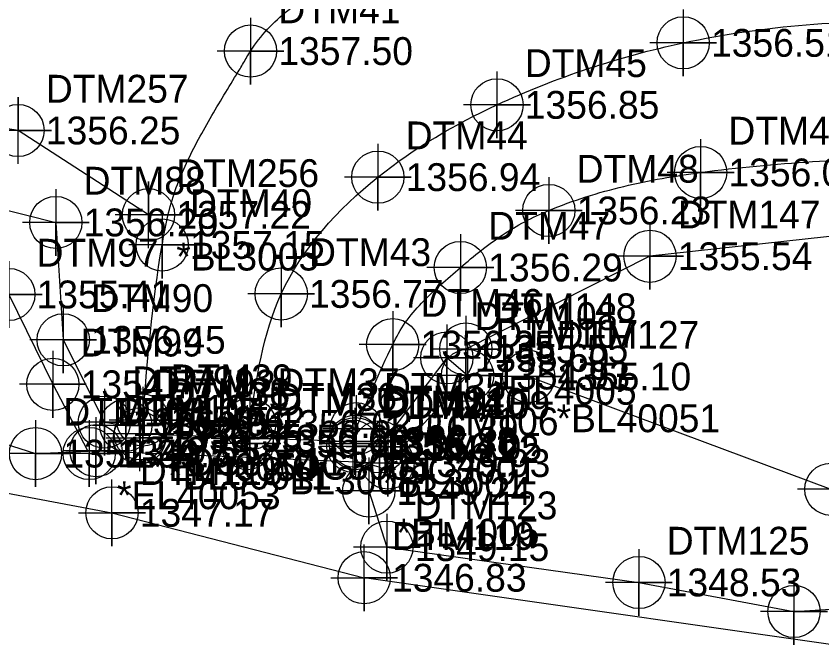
# Model space of a CAD drawing. Extents: x 1251905 to 1252853, y 859795 to 860170.
# Drawn here: x 1252015.3 to 1252087.6, y 860028.5 to 860085.2 of the extents above; entities that cross this region are included whole.
import ezdxf

# ---------------------------------------------------------------- set-up
doc = ezdxf.new("R2010")
doc.units = 0
for name, color, linetype in [('Cogo Default Point CELL', 7, 'Continuous'), ('COGO Default Point Elevation', 7, 'Continuous'), ('COGO Default Point Number', 7, 'Continuous'), ('Exist DTM Breakline', 7, 'Continuous'), ('Exist DTM Breakline Cogo Comment', 7, 'Continuous'), ('Exist DTM Breakline Cogo Elevation', 7, 'Continuous'), ('Exist DTM Breakline Cogo Number', 7, 'Continuous'), ('Exist DTM Breakline Cogo Point CELL', 7, 'Continuous'), ('Exist DTM Crownline', 7, 'Continuous'), ('Exist DTM Crownline Cogo Comment', 7, 'Continuous'), ('Exist DTM Crownline Cogo Elevation', 7, 'Continuous'), ('Exist DTM Crownline Cogo Number', 7, 'Continuous'), ('Exist DTM Crownline Cogo Point CELL', 7, 'Continuous'), ('Exist DTM Regular Point CELL', 7, 'Continuous'), ('Exist DTM Regular Point Cogo Elevation', 7, 'Continuous'), ('Exist DTM Regular Point Cogo Number', 7, 'Continuous'), ('Exist Hydro Stream or Body of Water', 7, 'Continuous'), ('Exist Hydro Stream or Body of Water Cogo Elevation', 7, 'Continuous'), ('Exist Hydro Stream or Body of Water Cogo Number', 7, 'Continuous'), ('Exist Hydro Stream or Body of Water Cogo Point CELL', 7, 'Continuous'), ('Exist Roads EOP', 7, 'Continuous'), ('Exist Roads EOP Cogo Comment', 7, 'Continuous'), ('Exist Roads EOP Cogo Elevation', 7, 'Continuous'), ('Exist Roads EOP Cogo Number', 7, 'Continuous'), ('Exist Roads EOP Cogo Point CELL', 7, 'Continuous'), ('Exist Roads Soil', 7, 'Continuous'), ('Exist Roads Soil Cogo Comment', 7, 'Continuous'), ('Exist Roads Soil Cogo Elevation', 7, 'Continuous'), ('Exist Roads Soil Cogo Number', 7, 'Continuous'), ('Exist Roads Soil Cogo Point CELL', 7, 'Continuous'), ('Exist Structure Major Deck Tunnel Box Culvert Cogo Elevation', 7, 'Continuous'), ('Exist Structure Major Deck Tunnel Box Culvert Cogo Number', 7, 'Continuous'), ('Exist Structure Major Deck Tunnel Box Culvert Cogo Point CELL', 7, 'Continuous')]:
    doc.layers.add(name, color=color, linetype=linetype)

msp = doc.modelspace()

# ---------------------------------------------------------------- linework, layer by layer
at = {"layer": 'Cogo Default Point CELL'}
for points in [[(1252045.737, 860049.7809999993), (1252045.737, 860046.7809999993)], [(1252042.737, 860046.7809999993), (1252045.737, 860046.7809999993)], [(1252045.737, 860046.7809999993), (1252048.737, 860046.7809999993)], [(1252045.737, 860046.7809999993), (1252045.737, 860043.7809999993)]]:
    msp.add_lwpolyline(points, dxfattribs=at)
msp.add_circle((1252045.737, 860046.7809999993), 2.344041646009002, dxfattribs=at)
at = {"layer": 'Exist DTM Breakline'}
for points in [[(1251930.158, 860079.966), (1251954.171, 860076.105), (1251996.545, 860072.28), (1252018.833, 860066.653), (1252019.501, 860056.104), (1252023.199, 860048.714), (1252025.121, 860048.4230000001)], [(1251929.364, 860075.1290000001), (1251953.388, 860071.501), (1251993.329, 860060.067), (1252014.61, 860060.183), (1252018.5690000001, 860052.108), (1252021.6546675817, 860046.2269804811)], [(1251926.999, 860067.532), (1251948.9880000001, 860060.189), (1251991.758, 860053.937), (1252017.01, 860045.885), (1252022.44, 860046.144), (1252048.6570000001, 860045.032), (1252055.807, 860052.8960000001), (1252053.946, 860054.482), (1252047.904, 860046.493)], [(1252212.143, 860042.894), (1252165.922, 860055.456), (1252123.408, 860063.782), (1252098.156, 860066.464), (1252072.182, 860063.615), (1252055.654, 860055.275)], [(1252061.299, 860052.806), (1252088.425, 860042.6780000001), (1252111.564, 860045.6680000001), (1252135.233, 860058.213), (1252169.648, 860048.881), (1252211.681, 860040.318)], [(1252046.935, 860042.529), (1252048.558, 860037.478), (1252071.192, 860034.305), (1252085.116, 860031.692), (1252110.305, 860033.296), (1252166.428, 860039.344), (1252210.773, 860033.4230000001)]]:
    msp.add_lwpolyline(points, dxfattribs=at)
at = {"layer": 'Exist DTM Breakline Cogo Point CELL'}
for points in [[(1252018.833, 860069.6529999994), (1252018.833, 860063.6529999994), (1252018.833, 860066.6529999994), (1252021.833, 860066.6529999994), (1252015.833, 860066.6529999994)], [(1252072.182, 860066.6149999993), (1252072.182, 860060.6149999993), (1252072.182, 860063.6149999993), (1252075.182, 860063.6149999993), (1252069.182, 860063.6149999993)], [(1252014.61, 860063.1829999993), (1252014.61, 860057.1829999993), (1252014.61, 860060.1829999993), (1252017.61, 860060.1829999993), (1252011.61, 860060.1829999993)], [(1252019.501, 860059.1039999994), (1252019.501, 860053.1039999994), (1252019.501, 860056.1039999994), (1252022.501, 860056.1039999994), (1252016.501, 860056.1039999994)], [(1252055.654, 860058.2749999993), (1252055.654, 860052.2749999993), (1252055.654, 860055.2749999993), (1252058.654, 860055.2749999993), (1252052.654, 860055.2749999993)], [(1252053.946, 860057.4819999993), (1252053.946, 860051.4819999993), (1252053.946, 860054.4819999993), (1252056.946, 860054.4819999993), (1252050.946, 860054.4819999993)], [(1252055.807, 860055.8959999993), (1252055.807, 860049.8959999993), (1252055.807, 860052.8959999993), (1252058.807, 860052.8959999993), (1252052.807, 860052.8959999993)], [(1252061.299, 860055.8059999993), (1252061.299, 860049.8059999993), (1252061.299, 860052.8059999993), (1252064.299, 860052.8059999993), (1252058.299, 860052.8059999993)], [(1252018.5690000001, 860055.1079999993), (1252018.5690000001, 860049.1079999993), (1252018.5690000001, 860052.1079999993), (1252021.5690000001, 860052.1079999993), (1252015.5690000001, 860052.1079999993)], [(1252023.199, 860051.7139999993), (1252023.199, 860045.7139999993), (1252023.199, 860048.7139999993), (1252026.199, 860048.7139999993), (1252020.199, 860048.7139999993)], [(1252025.121, 860051.4229999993), (1252025.121, 860045.4229999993), (1252025.121, 860048.4229999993), (1252028.121, 860048.4229999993), (1252022.121, 860048.4229999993)], [(1252047.904, 860049.4929999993), (1252047.904, 860043.4929999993), (1252047.904, 860046.4929999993), (1252050.904, 860046.4929999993), (1252044.904, 860046.4929999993)], [(1252017.01, 860048.8849999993), (1252017.01, 860042.8849999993), (1252017.01, 860045.8849999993), (1252020.01, 860045.8849999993), (1252014.01, 860045.8849999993)], [(1252021.832, 860048.8889999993), (1252021.832, 860042.8889999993), (1252021.832, 860045.8889999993), (1252024.832, 860045.8889999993), (1252018.832, 860045.8889999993)], [(1252022.44, 860049.1439999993), (1252022.44, 860043.1439999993), (1252022.44, 860046.1439999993), (1252025.44, 860046.1439999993), (1252019.44, 860046.1439999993)], [(1252048.6570000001, 860048.0319999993), (1252048.6570000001, 860042.0319999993), (1252048.6570000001, 860045.0319999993), (1252051.6570000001, 860045.0319999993), (1252045.6570000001, 860045.0319999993)], [(1252088.425, 860045.6779999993), (1252088.425, 860039.6779999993), (1252088.425, 860042.6779999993), (1252091.425, 860042.6779999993), (1252085.425, 860042.6779999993)], [(1252046.935, 860045.5289999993), (1252046.935, 860039.5289999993), (1252046.935, 860042.5289999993), (1252049.935, 860042.5289999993), (1252043.935, 860042.5289999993)], [(1252048.558, 860040.4779999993), (1252048.558, 860034.4779999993), (1252048.558, 860037.4779999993), (1252051.558, 860037.4779999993), (1252045.558, 860037.4779999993)], [(1252071.192, 860037.3049999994), (1252071.192, 860031.3049999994), (1252071.192, 860034.3049999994), (1252074.192, 860034.3049999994), (1252068.192, 860034.3049999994)], [(1252085.116, 860034.6919999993), (1252085.116, 860028.6919999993), (1252085.116, 860031.6919999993), (1252088.116, 860031.6919999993), (1252082.116, 860031.6919999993)]]:
    msp.add_lwpolyline(points, dxfattribs=at)
for centre in [(1252018.833, 860066.6529999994), (1252072.182, 860063.6149999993), (1252014.61, 860060.1829999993), (1252019.501, 860056.1039999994), (1252055.654, 860055.2749999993), (1252053.946, 860054.4819999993), (1252055.807, 860052.8959999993), (1252061.299, 860052.8059999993), (1252018.5690000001, 860052.1079999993), (1252023.199, 860048.7139999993), (1252025.121, 860048.4229999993), (1252047.904, 860046.4929999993), (1252017.01, 860045.8849999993), (1252021.832, 860045.8889999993), (1252022.44, 860046.1439999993), (1252048.6570000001, 860045.0319999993), (1252088.425, 860042.6779999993), (1252046.935, 860042.5289999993), (1252048.558, 860037.4779999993), (1252071.192, 860034.3049999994), (1252085.116, 860031.6919999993)]:
    msp.add_circle(centre, 2.344041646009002, dxfattribs=at)
at = {"layer": 'Exist DTM Crownline'}
msp.add_line((1252036.0382223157, 860047.3657758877), (1252036.243, 860048.539), dxfattribs=at)
msp.add_spline([(1252036.243, 860048.539), (1252039.0760000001, 860060.231), (1252047.752, 860070.723), (1252058.446, 860077.2170000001), (1252075.17, 860082.787), (1252097.364, 860084.644), (1252123.933, 860080.792), (1252172.517, 860069.427), (1252214.359, 860058.511)], degree=3, dxfattribs=at)
at = {"layer": 'Exist DTM Crownline Cogo Point CELL'}
for points in [[(1252075.17, 860085.7869999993), (1252075.17, 860079.7869999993), (1252075.17, 860082.7869999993), (1252078.17, 860082.7869999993), (1252072.17, 860082.7869999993)], [(1252058.446, 860080.2169999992), (1252058.446, 860074.2169999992), (1252058.446, 860077.2169999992), (1252061.446, 860077.2169999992), (1252055.446, 860077.2169999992)], [(1252047.752, 860073.7229999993), (1252047.752, 860067.7229999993), (1252047.752, 860070.7229999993), (1252050.752, 860070.7229999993), (1252044.752, 860070.7229999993)], [(1252039.0760000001, 860063.2309999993), (1252039.0760000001, 860057.2309999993), (1252039.0760000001, 860060.2309999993), (1252042.0760000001, 860060.2309999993), (1252036.0760000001, 860060.2309999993)], [(1252036.243, 860051.5389999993), (1252036.243, 860045.5389999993), (1252036.243, 860048.5389999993), (1252039.243, 860048.5389999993), (1252033.243, 860048.5389999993)], [(1252036.014, 860050.2269999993), (1252036.014, 860044.2269999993), (1252036.014, 860047.2269999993), (1252039.014, 860047.2269999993), (1252033.014, 860047.2269999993)]]:
    msp.add_lwpolyline(points, dxfattribs=at)
for centre in [(1252075.17, 860082.7869999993), (1252058.446, 860077.2169999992), (1252047.752, 860070.7229999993), (1252039.0760000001, 860060.2309999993), (1252036.243, 860048.5389999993), (1252036.014, 860047.2269999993)]:
    msp.add_circle(centre, 2.344041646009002, dxfattribs=at)
at = {"layer": 'Exist DTM Regular Point CELL'}
msp.add_lwpolyline([(1252036.0320000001, 860049.7829999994), (1252036.0320000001, 860043.7829999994), (1252036.0320000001, 860046.7829999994), (1252039.0320000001, 860046.7829999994), (1252033.0320000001, 860046.7829999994)], dxfattribs=at)
msp.add_circle((1252036.0320000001, 860046.7829999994), 2.344041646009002, dxfattribs=at)
at = {"layer": 'Exist Hydro Stream or Body of Water'}
for points in [[(1251931.145, 860058.535), (1251964.012, 860051.9450000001), (1251993.851, 860046.208), (1252023.877, 860040.562), (1252046.52, 860034.729)], [(1252097.617, 860027.4109999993), (1252046.52, 860034.7289999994)]]:
    msp.add_lwpolyline(points, dxfattribs=at)
at = {"layer": 'Exist Hydro Stream or Body of Water Cogo Point CELL'}
for points in [[(1252020.877, 860040.5619999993), (1252026.877, 860040.5619999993), (1252023.877, 860040.5619999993), (1252023.877, 860037.5619999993), (1252023.877, 860043.5619999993)], [(1252043.52, 860034.7289999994), (1252049.52, 860034.7289999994), (1252046.52, 860034.7289999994), (1252046.52, 860031.7289999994), (1252046.52, 860037.7289999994)]]:
    msp.add_lwpolyline(points, dxfattribs=at)
for centre in [(1252023.877, 860040.5619999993), (1252046.52, 860034.7289999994)]:
    msp.add_circle(centre, 2.344041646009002, dxfattribs=at)
at = {"layer": 'Exist Roads EOP'}
for p, q in [((1252026.419, 860047.657), (1252026.637, 860048.895)), ((1252045.697, 860046.985), (1252045.803, 860048.12))]:
    msp.add_line(p, q, dxfattribs=at)
msp.add_lwpolyline([(1252026.419, 860047.6569999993), (1252045.697, 860046.985)], dxfattribs=at)
for points in [[(1252026.637, 860048.895), (1252028.382, 860064.631), (1252029.450817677, 860069.2266718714), (1252031.3665109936, 860073.5830663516), (1252033.7746988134, 860077.8181776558), (1252035.052734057, 860079.9271253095), (1252035.6908567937, 860080.9858999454), (1252036.321, 860082.05), (1252039.680538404, 860085.7023063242), (1252044.1481441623, 860088.5391813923), (1252048.5199278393, 860090.7119657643), (1252051.5919999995, 860092.3719999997)], [(1252045.803, 860048.12), (1252049.087, 860055.674), (1252050.2153975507, 860057.6515921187), (1252051.6839917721, 860059.4129647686), (1252053.3720901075, 860061.0363550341), (1252055.159, 860062.6), (1252057.0142268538, 860064.1325732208), (1252058.9250323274, 860065.5135143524), (1252060.9378216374, 860066.7191983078), (1252063.099, 860067.726), (1252069.836107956, 860069.8939456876), (1252076.731, 860071.145), (1252086.7906137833, 860072.1203664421), (1252096.85, 860072.458), (1252103.1642067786, 860072.2657761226), (1252109.4781924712, 860071.8459595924), (1252115.7920819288, 860071.306163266), (1252122.106, 860070.7540000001), (1252128.211654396, 860069.9862457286), (1252134.2921622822, 860068.7856334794), (1252146.3586576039, 860065.6279820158), (1252158.2673241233, 860062.3653395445), (1252164.150546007, 860061.0334885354), (1252169.98, 860060.082), (1252169.9800000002, 860060.082)]]:
    msp.add_spline(points, degree=3, dxfattribs=at)
at = {"layer": 'Exist Roads EOP Cogo Point CELL'}
for points in [[(1252036.321, 860085.0499999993), (1252036.321, 860079.0499999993), (1252036.321, 860082.0499999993), (1252039.321, 860082.0499999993), (1252033.321, 860082.0499999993)], [(1252076.731, 860074.1449999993), (1252076.731, 860068.1449999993), (1252076.731, 860071.1449999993), (1252079.731, 860071.1449999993), (1252073.731, 860071.1449999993)], [(1252063.099, 860070.7259999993), (1252063.099, 860064.7259999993), (1252063.099, 860067.7259999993), (1252066.099, 860067.7259999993), (1252060.099, 860067.7259999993)], [(1252028.382, 860067.6309999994), (1252028.382, 860061.6309999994), (1252028.382, 860064.6309999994), (1252031.382, 860064.6309999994), (1252025.382, 860064.6309999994)], [(1252055.159, 860065.5999999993), (1252055.159, 860059.5999999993), (1252055.159, 860062.5999999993), (1252058.159, 860062.5999999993), (1252052.159, 860062.5999999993)], [(1252049.087, 860058.6739999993), (1252049.087, 860052.6739999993), (1252049.087, 860055.6739999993), (1252052.087, 860055.6739999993), (1252046.087, 860055.6739999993)], [(1252026.637, 860051.8949999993), (1252026.637, 860045.8949999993), (1252026.637, 860048.8949999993), (1252029.637, 860048.8949999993), (1252023.637, 860048.8949999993)], [(1252045.803, 860051.1199999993), (1252045.803, 860045.1199999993), (1252045.803, 860048.1199999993), (1252048.803, 860048.1199999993), (1252042.803, 860048.1199999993)], [(1252026.419, 860050.6569999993), (1252026.419, 860044.6569999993), (1252026.419, 860047.6569999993), (1252029.419, 860047.6569999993), (1252023.419, 860047.6569999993)], [(1252045.697, 860049.9849999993), (1252045.697, 860043.9849999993), (1252045.697, 860046.9849999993), (1252048.697, 860046.9849999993), (1252042.697, 860046.9849999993)]]:
    msp.add_lwpolyline(points, dxfattribs=at)
for centre in [(1252036.321, 860082.0499999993), (1252076.731, 860071.1449999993), (1252063.099, 860067.7259999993), (1252028.382, 860064.6309999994), (1252055.159, 860062.5999999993), (1252049.087, 860055.6739999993), (1252026.637, 860048.8949999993), (1252026.419, 860047.6569999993), (1252045.803, 860048.1199999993), (1252045.697, 860046.9849999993)]:
    msp.add_circle(centre, 2.344041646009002, dxfattribs=at)
at = {"layer": 'Exist Roads Soil'}
msp.add_lwpolyline([(1252027.154, 860067.333), (1252015.44, 860074.915), (1251989.358, 860079.095), (1251956.453, 860081.7540000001)], dxfattribs=at)
at = {"layer": 'Exist Roads Soil Cogo Point CELL'}
for points in [[(1252015.44, 860071.9149999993), (1252015.44, 860077.9149999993), (1252015.44, 860074.9149999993), (1252018.44, 860074.9149999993), (1252012.44, 860074.9149999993)], [(1252027.154, 860064.3329999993), (1252027.154, 860070.3329999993), (1252027.154, 860067.3329999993), (1252030.154, 860067.3329999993), (1252024.154, 860067.3329999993)]]:
    msp.add_lwpolyline(points, dxfattribs=at)
for centre in [(1252015.44, 860074.9149999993), (1252027.154, 860067.3329999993)]:
    msp.add_circle(centre, 2.344041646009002, dxfattribs=at)
at = {"layer": 'Exist Structure Major Deck Tunnel Box Culvert Cogo Point CELL'}
for points in [[(1252023.352, 860047.2989999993), (1252029.352, 860047.2989999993), (1252026.352, 860047.2989999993), (1252026.352, 860050.2989999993), (1252026.352, 860044.2989999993)], [(1252042.5050000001, 860046.5489999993), (1252048.5050000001, 860046.5489999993), (1252045.5050000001, 860046.5489999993), (1252045.5050000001, 860049.5489999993), (1252045.5050000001, 860043.5489999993)]]:
    msp.add_lwpolyline(points, dxfattribs=at)
for centre in [(1252026.352, 860047.2989999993), (1252045.5050000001, 860046.5489999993)]:
    msp.add_circle(centre, 2.344041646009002, dxfattribs=at)

# ---------------------------------------------------------------- texts
at = {"layer": 'COGO Default Point Elevation'}
msp.add_text('1356.46', height=2.5, dxfattribs=at).set_placement((1252048.237, 860045.5310000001))
at = {"layer": 'COGO Default Point Number'}
msp.add_text('DTM110', height=2.5, dxfattribs=at).set_placement((1252048.237, 860049.2810000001))
at = {"layer": 'Exist DTM Breakline Cogo Comment'}
for s, p in [('*EL4005', (1252058.154, 860050.275)), ('*BL40051', (1252063.799, 860047.806)), ('*EL40054', (1252027.621, 860043.4230000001)), ('*EL40053', (1252024.332, 860040.889)), ('*BL4005', (1252049.435, 860037.529))]:
    msp.add_text(s, height=2.5, dxfattribs=at).set_placement(p)
at = {"layer": 'Exist DTM Breakline Cogo Elevation'}
for s, p in [('1356.20', (1252021.333, 860065.403)), ('1355.54', (1252074.682, 860062.365)), ('1355.41', (1252017.11, 860058.933)), ('1356.45', (1252022.001, 860054.854)), ('1355.55', (1252058.154, 860054.025)), ('1355.60', (1252056.446, 860053.232)), ('1354.93', (1252058.307, 860051.6460000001)), ('1355.10', (1252063.799, 860051.556)), ('1354.77', (1252021.0690000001, 860050.858)), ('1356.49', (1252025.699, 860047.464)), ('1356.61', (1252027.621, 860047.1730000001)), ('1352.34', (1252019.51, 860044.635)), ('1349.56', (1252024.332, 860044.639)), ('1349.55', (1252024.94, 860044.894)), ('1356.05', (1252050.404, 860045.243)), ('1349.93', (1252051.1570000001, 860043.782)), ('1349.24', (1252049.435, 860041.279)), ('1349.15', (1252051.058, 860036.228)), ('1348.53', (1252073.692, 860033.055))]:
    msp.add_text(s, height=2.5, dxfattribs=at).set_placement(p)
at = {"layer": 'Exist DTM Breakline Cogo Number'}
for s, p in [('DTM88', (1252021.333, 860069.153)), ('DTM147', (1252074.682, 860066.115)), ('DTM97', (1252017.11, 860062.683)), ('DTM90', (1252022.001, 860058.604)), ('DTM148', (1252058.154, 860057.775)), ('DTM108', (1252056.446, 860056.982)), ('DTM107', (1252058.307, 860055.3960000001)), ('DTM127', (1252063.799, 860055.306)), ('DTM99', (1252021.0690000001, 860054.608)), ('DTM91', (1252025.699, 860051.214)), ('DTM92', (1252027.621, 860050.9230000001)), ('DTM109', (1252050.404, 860048.993)), ('DTM103', (1252019.51, 860048.385)), ('DTM105', (1252024.332, 860048.389)), ('DTM104', (1252024.94, 860048.644)), ('DTM106', (1252051.1570000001, 860047.532)), ('DTM122', (1252049.435, 860045.029)), ('DTM123', (1252051.058, 860039.978)), ('DTM125', (1252073.692, 860036.805))]:
    msp.add_text(s, height=2.5, dxfattribs=at).set_placement(p)
at = {"layer": 'Exist DTM Crownline Cogo Comment'}
for s, p in [('*OC3008', (1252038.743, 860043.539)), ('*BL3008', (1252038.514, 860042.2270000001))]:
    msp.add_text(s, height=2.5, dxfattribs=at).set_placement(p)
at = {"layer": 'Exist DTM Crownline Cogo Elevation'}
for s, p in [('1356.51', (1252077.67, 860081.537)), ('1356.85', (1252060.946, 860075.9670000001)), ('1356.94', (1252050.252, 860069.473)), ('1356.77', (1252041.5760000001, 860058.981)), ('1356.62', (1252038.743, 860047.289)), ('1356.63', (1252038.514, 860045.9770000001))]:
    msp.add_text(s, height=2.5, dxfattribs=at).set_placement(p)
at = {"layer": 'Exist DTM Crownline Cogo Number'}
for s, p in [('DTM45', (1252060.946, 860079.7170000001)), ('DTM44', (1252050.252, 860073.223)), ('DTM43', (1252041.5760000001, 860062.731)), ('DTM37', (1252038.743, 860051.039)), ('DTM36', (1252038.514, 860049.7270000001))]:
    msp.add_text(s, height=2.5, dxfattribs=at).set_placement(p)
at = {"layer": 'Exist DTM Regular Point Cogo Elevation'}
msp.add_text('1356.63', height=2.5, dxfattribs=at).set_placement((1252038.5320000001, 860045.533))
at = {"layer": 'Exist DTM Regular Point Cogo Number'}
msp.add_text('DTM27', height=2.5, dxfattribs=at).set_placement((1252038.5320000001, 860049.283))
at = {"layer": 'Exist Hydro Stream or Body of Water Cogo Elevation'}
for s, p in [('1347.17', (1252026.377, 860039.312)), ('1346.83', (1252049.02, 860033.479))]:
    msp.add_text(s, height=2.5, dxfattribs=at).set_placement(p)
at = {"layer": 'Exist Hydro Stream or Body of Water Cogo Number'}
for s, p in [('DTM118', (1252026.377, 860043.062)), ('DTM119', (1252049.02, 860037.229))]:
    msp.add_text(s, height=2.5, dxfattribs=at).set_placement(p)
at = {"layer": 'Exist Roads EOP Cogo Comment'}
for s, p in [('*OC30011', (1252029.137, 860043.895)), ('*OC3001', (1252048.303, 860043.12)), ('*BL30011', (1252028.919, 860042.657)), ('*BL3001', (1252048.197, 860041.985))]:
    msp.add_text(s, height=2.5, dxfattribs=at).set_placement(p)
at = {"layer": 'Exist Roads EOP Cogo Elevation'}
for s, p in [('1357.50', (1252038.821, 860080.8)), ('1356.03', (1252079.231, 860069.895)), ('1356.23', (1252065.599, 860066.476)), ('1357.15', (1252030.882, 860063.381)), ('1356.29', (1252057.659, 860061.35)), ('1356.35', (1252051.587, 860054.424)), ('1356.62', (1252029.137, 860047.645)), ('1356.39', (1252048.303, 860046.87)), ('1356.55', (1252028.919, 860046.407)), ('1356.38', (1252048.197, 860045.735))]:
    msp.add_text(s, height=2.5, dxfattribs=at).set_placement(p)
at = {"layer": 'Exist Roads EOP Cogo Number'}
for s, p in [('DTM41', (1252038.821, 860084.55)), ('DTM49', (1252079.231, 860073.645)), ('DTM48', (1252065.599, 860070.226)), ('DTM40', (1252030.882, 860067.131)), ('DTM47', (1252057.659, 860065.1)), ('DTM46', (1252051.587, 860058.174)), ('DTM39', (1252029.137, 860051.395)), ('DTM35', (1252048.303, 860050.62)), ('DTM38', (1252028.919, 860050.157)), ('DTM34', (1252048.197, 860049.485))]:
    msp.add_text(s, height=2.5, dxfattribs=at).set_placement(p)
at = {"layer": 'Exist Roads Soil Cogo Comment'}
msp.add_text('*BL3005', height=2.5, dxfattribs=at).set_placement((1252029.654, 860062.333))
at = {"layer": 'Exist Roads Soil Cogo Elevation'}
for s, p in [('1356.25', (1252017.94, 860073.665)), ('1357.22', (1252029.654, 860066.083))]:
    msp.add_text(s, height=2.5, dxfattribs=at).set_placement(p)
at = {"layer": 'Exist Roads Soil Cogo Number'}
for s, p in [('DTM257', (1252017.94, 860077.415)), ('DTM256', (1252029.654, 860069.833))]:
    msp.add_text(s, height=2.5, dxfattribs=at).set_placement(p)
at = {"layer": 'Exist Structure Major Deck Tunnel Box Culvert Cogo Elevation'}
for s, p in [('1356.55', (1252028.852, 860046.049)), ('1356.41', (1252048.0050000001, 860045.299))]:
    msp.add_text(s, height=2.5, dxfattribs=at).set_placement(p)
at = {"layer": 'Exist Structure Major Deck Tunnel Box Culvert Cogo Number'}
for s, p in [('DTM25', (1252028.852, 860049.799)), ('DTM24', (1252048.0050000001, 860049.049))]:
    msp.add_text(s, height=2.5, dxfattribs=at).set_placement(p)

doc.saveas('drawing.dxf')
